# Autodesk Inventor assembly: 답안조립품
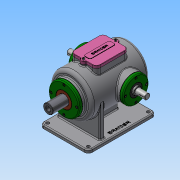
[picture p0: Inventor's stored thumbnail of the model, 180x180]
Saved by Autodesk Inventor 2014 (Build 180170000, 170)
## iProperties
Created: 2020-08
Part Number: 답안조립품
Document SubType Name: Assembly
Designer: net
Author: net
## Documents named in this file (15)
- C:\Users\net\Desktop\600806V1036\답안조립품.iam
- C:\Users\net\Desktop\600806V1036\본체.ipt
- C:\Users\net\Desktop\600806V1036\개스킷 B.ipt
- C:\Users\net\Desktop\600806V1036\개스킷 A.ipt
- C:\Users\net\Desktop\600806V1036\상부커버.ipt
- C:\Users\net\Desktop\600806V1036\베어링 6205.ipt
- 베어링 6205.ipt
- C:\Users\net\Desktop\600806V1036\축 커버.ipt
- C:\Users\net\Desktop\600806V1036\볼트 M4.ipt
- C:\Users\net\Desktop\600806V1036\슬라이드 커버.ipt
- C:\Users\net\Desktop\600806V1036\부시.ipt
- C:\Users\net\Desktop\600806V1036\오일 실 25 38 8.ipt
- C:\Users\net\Desktop\600806V1036\편심축.ipt
- C:\Users\net\Desktop\600806V1036\슬라이드.ipt
- C:\Users\net\Desktop\600806V1036\가변스프링.ipt
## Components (4 placed, 3 different names)
1. 개스킷 B:1
2. 개스킷 B:2
3. 개스킷 A:1
4. 가변스프링:1
